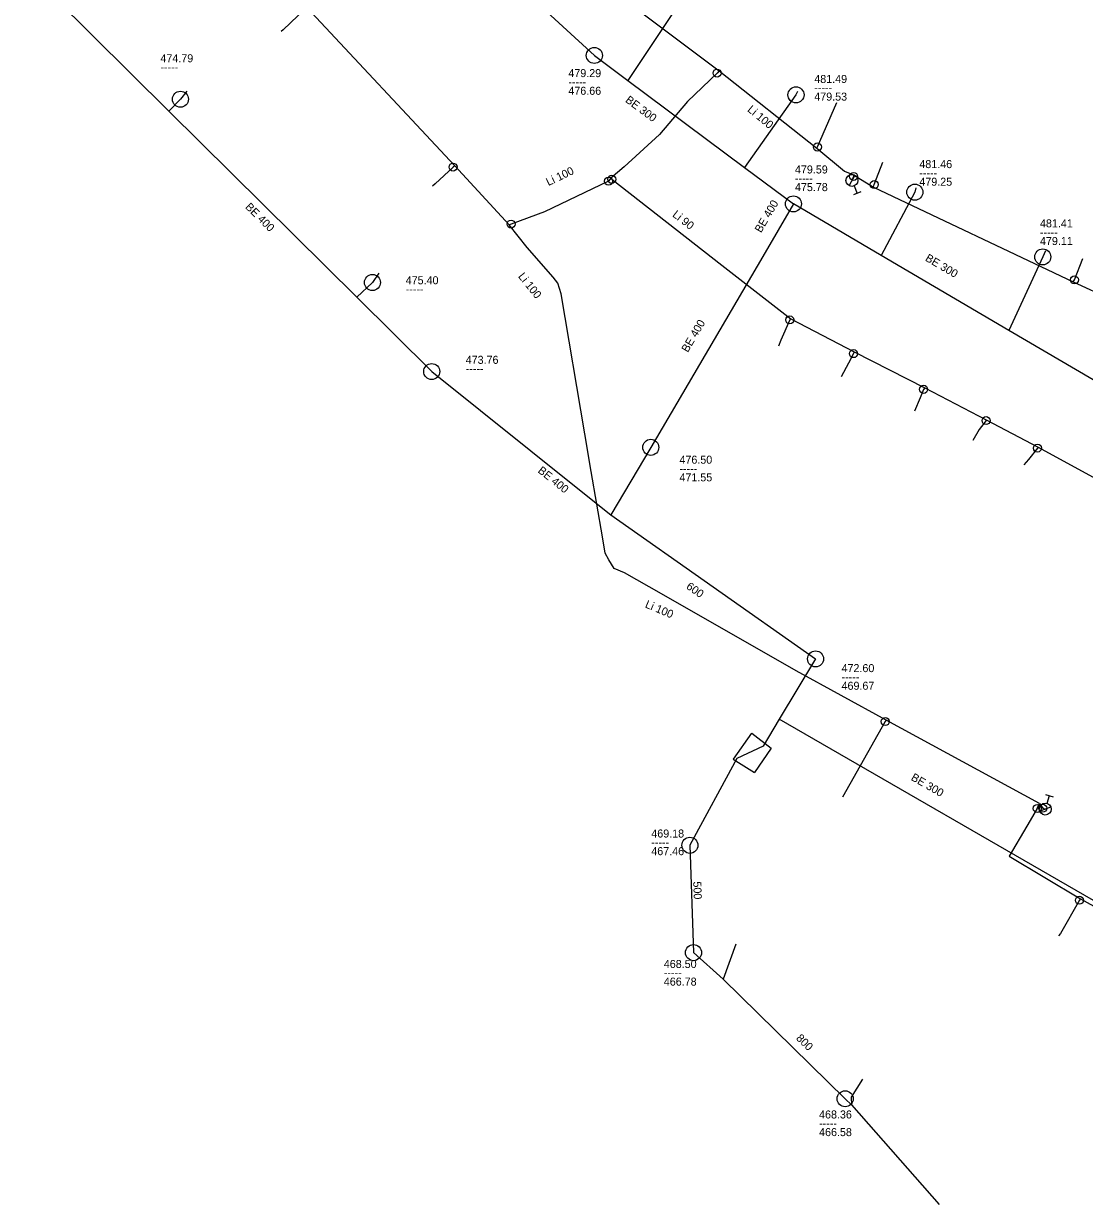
# Model space of a CAD drawing. Extents: x -685576 to -685145, y -1163436 to -1162895.
# Drawn here: x -685400.1 to -685267.9, y -1163416.2 to -1163269 of the extents above; entities that cross this region are included whole.
import ezdxf

# ---------------------------------------------------------------- set-up
doc = ezdxf.new("R2010")
doc.units = 0
doc.layers.add('Level 0', color=7, linetype='Continuous')

msp = doc.modelspace()

# ---------------------------------------------------------------- linework, layer by layer
at = {"layer": 'Level 0'}
for p, q in [((-685400.12, -1163261.95), (-685382.02, -1163279.88)), ((-685340, -1163262.77), (-685328.96, -1163272.95)), ((-685365.02, -1163267.13), (-685367.75, -1163269.74)), ((-685346.37, -1163286.69), (-685364.83, -1163266.94)), ((-685318.54, -1163266.73), (-685324.77, -1163276.07)), ((-685324.37, -1163266.65), (-685313.39, -1163274.86)), ((-685367.75, -1163269.74), (-685367.99, -1163269.96)), ((-685328.96, -1163272.95), (-685324.77, -1163276.07)), ((-685313.39, -1163274.86), (-685313.66, -1163275.14)), ((-685313.39, -1163274.86), (-685301.22, -1163284.5)), ((-685324.77, -1163276.07), (-685310.25, -1163286.9)), ((-685313.66, -1163275.14), (-685317.36, -1163278.7)), ((-685379.76, -1163277.4), (-685380.57, -1163278.41)), ((-685303.82, -1163277.86), (-685310.25, -1163286.9)), ((-685303.62, -1163277.45), (-685303.82, -1163277.86)), ((-685380.57, -1163278.41), (-685382.02, -1163279.88)), ((-685317.36, -1163278.7), (-685320.83, -1163282.81)), ((-685301.15, -1163284.36), (-685298.74, -1163278.82)), ((-685382.02, -1163279.88), (-685358.59, -1163303.09)), ((-685320.83, -1163282.81), (-685325.26, -1163286.83)), ((-685301.22, -1163284.5), (-685301.15, -1163284.36)), ((-685301.22, -1163284.5), (-685297.78, -1163287.36)), ((-685346.37, -1163286.69), (-685346.58, -1163286.86)), ((-685339.58, -1163294.07), (-685346.37, -1163286.69)), ((-685294.06, -1163289.04), (-685293, -1163286.26)), ((-685346.58, -1163286.86), (-685348.82, -1163288.94)), ((-685325.26, -1163286.83), (-685326.9, -1163288.26)), ((-685310.25, -1163286.9), (-685304.14, -1163291.45)), ((-685297.78, -1163287.36), (-685296.66, -1163287.81)), ((-685296.47, -1163287.87), (-685297.21, -1163289.17)), ((-685296.64, -1163288.03), (-685296.84, -1163288.52)), ((-685296.66, -1163287.81), (-685294.17, -1163289.38)), ((-685296.66, -1163287.81), (-685296.64, -1163288.03)), ((-685348.82, -1163288.94), (-685349.12, -1163289.26)), ((-685327.19, -1163288.62), (-685335.17, -1163292.44)), ((-685326.9, -1163288.26), (-685327.19, -1163288.62)), ((-685326.9, -1163288.26), (-685326.79, -1163288.39)), ((-685326.79, -1163288.39), (-685313.05, -1163299.09)), ((-685296.56, -1163289.21), (-685296.18, -1163290.14)), ((-685294.17, -1163289.38), (-685294.06, -1163289.04)), ((-685294.17, -1163289.38), (-685269.25, -1163301.17)), ((-685288.88, -1163289.44), (-685289, -1163289.99)), ((-685295.72, -1163289.95), (-685296.64, -1163290.33)), ((-685289, -1163289.99), (-685293.2, -1163297.88)), ((-685335.17, -1163292.44), (-685339.34, -1163293.97)), ((-685304.14, -1163291.45), (-685307.97, -1163297.99)), ((-685293.2, -1163297.88), (-685304.14, -1163291.45)), ((-685339.34, -1163293.97), (-685339.58, -1163294.07)), ((-685337.33, -1163296.89), (-685339.58, -1163294.07)), ((-685334.11, -1163300.6), (-685337.33, -1163296.89)), ((-685307.97, -1163297.99), (-685321.93, -1163321.8)), ((-685277.28, -1163307.23), (-685293.2, -1163297.88)), ((-685273.05, -1163298.06), (-685277.28, -1163307.23)), ((-685272.69, -1163297.29), (-685273.05, -1163298.06)), ((-685269.11, -1163300.92), (-685268.07, -1163298.27)), ((-685313.05, -1163299.09), (-685304.45, -1163305.78)), ((-685356.63, -1163301.25), (-685358.56, -1163303.06)), ((-685355.84, -1163300.09), (-685356.63, -1163301.25)), ((-685333.51, -1163301.35), (-685334.11, -1163300.6)), ((-685333.11, -1163302.67), (-685333.51, -1163301.35)), ((-685269.25, -1163301.17), (-685269.11, -1163300.92)), ((-685269.25, -1163301.17), (-685261.75, -1163304.63)), ((-685330.16, -1163320.11), (-685333.11, -1163302.67)), ((-685358.56, -1163303.06), (-685358.59, -1163303.09)), ((-685358.59, -1163303.09), (-685349.24, -1163312.35)), ((-685304.45, -1163305.78), (-685304.59, -1163305.91)), ((-685304.45, -1163305.78), (-685296.55, -1163309.9)), ((-685304.59, -1163305.91), (-685305.72, -1163308.42)), ((-685260.91, -1163316.85), (-685277.28, -1163307.23)), ((-685305.72, -1163308.42), (-685306.02, -1163309.17)), ((-685296.65, -1163310.12), (-685297.27, -1163311.3)), ((-685296.55, -1163309.9), (-685296.65, -1163310.12)), ((-685296.55, -1163309.9), (-685287.77, -1163314.37)), ((-685297.27, -1163311.3), (-685298.18, -1163313.03)), ((-685349.24, -1163312.35), (-685330.8, -1163327.11)), ((-685287.91, -1163314.57), (-685288.35, -1163315.61)), ((-685287.77, -1163314.37), (-685287.91, -1163314.57)), ((-685287.77, -1163314.37), (-685280.09, -1163318.38)), ((-685288.35, -1163315.61), (-685289.06, -1163317.27)), ((-685280.12, -1163318.47), (-685280.99, -1163319.59)), ((-685280.09, -1163318.38), (-685280.12, -1163318.47)), ((-685280.09, -1163318.38), (-685273.62, -1163321.79)), ((-685329.35, -1163324.82), (-685330.16, -1163320.11)), ((-685280.99, -1163319.59), (-685281.75, -1163320.94)), ((-685321.93, -1163321.8), (-685326.91, -1163330.22)), ((-685273.71, -1163321.9), (-685274.84, -1163323.31)), ((-685273.62, -1163321.79), (-685273.71, -1163321.9)), ((-685273.62, -1163321.79), (-685263.03, -1163327.59)), ((-685274.84, -1163323.31), (-685275.42, -1163323.97)), ((-685327.94, -1163332.97), (-685329.35, -1163324.82)), ((-685330.8, -1163327.11), (-685326.91, -1163330.22)), ((-685326.91, -1163330.22), (-685301.38, -1163348.17)), ((-685327.62, -1163334.98), (-685327.94, -1163332.97)), ((-685327.15, -1163335.84), (-685327.62, -1163334.98)), ((-685326.51, -1163336.91), (-685327.15, -1163335.84)), ((-685325.22, -1163337.45), (-685326.51, -1163336.91)), ((-685320.57, -1163340.07), (-685325.22, -1163337.45)), ((-685303.81, -1163349.68), (-685320.57, -1163340.07)), ((-685301.38, -1163348.17), (-685305.9, -1163355.68)), ((-685292.59, -1163355.81), (-685303.81, -1163349.68)), ((-685305.9, -1163355.68), (-685307.93, -1163359.03)), ((-685258.67, -1163382.95), (-685305.9, -1163355.68)), ((-685292.59, -1163355.81), (-685292.69, -1163355.98)), ((-685273.46, -1163366.21), (-685292.59, -1163355.81)), ((-685292.69, -1163355.98), (-685298.03, -1163365.42)), ((-685309.35, -1163357.41), (-685311.67, -1163360.66)), ((-685309.34, -1163357.42), (-685306.91, -1163359.28)), ((-685307.93, -1163359.03), (-685311.2, -1163360.6)), ((-685306.91, -1163359.28), (-685308.98, -1163362.32)), ((-685311.2, -1163360.6), (-685317.05, -1163371.41)), ((-685311.67, -1163360.66), (-685308.98, -1163362.32)), ((-685272.7, -1163365.07), (-685271.74, -1163365.37)), ((-685272.52, -1163366.17), (-685272.22, -1163365.22)), ((-685273.74, -1163366.82), (-685275.02, -1163369.01)), ((-685273.74, -1163366.82), (-685273.46, -1163366.21)), ((-685273.46, -1163366.21), (-685273.06, -1163366.79)), ((-685273.44, -1163367.16), (-685272.04, -1163366.62)), ((-685273.06, -1163366.79), (-685272.74, -1163366.89)), ((-685275.02, -1163369.01), (-685277.23, -1163372.76)), ((-685317.05, -1163371.41), (-685316.6, -1163384.79)), ((-685277.23, -1163372.76), (-685268.35, -1163378.09)), ((-685268.48, -1163378.26), (-685270.83, -1163382.4)), ((-685268.35, -1163378.09), (-685268.48, -1163378.26)), ((-685268.35, -1163378.09), (-685232.79, -1163397.77)), ((-685270.83, -1163382.4), (-685271.07, -1163382.7)), ((-685311.3, -1163383.73), (-685312.9, -1163388.11)), ((-685316.6, -1163384.79), (-685312.9, -1163388.11)), ((-685312.9, -1163388.11), (-685297.69, -1163403)), ((-685295.51, -1163400.57), (-685296.93, -1163402.8)), ((-685297.69, -1163403), (-685296.91, -1163403.76)), ((-685296.93, -1163402.8), (-685296.91, -1163403.76)), ((-685296.91, -1163403.76), (-685285.96, -1163416.17))]:
    msp.add_line(p, q, dxfattribs=at)
for centre, radius in [((-685328.96, -1163272.95), 1), ((-685313.66, -1163275.14), 0.5), ((-685380.57, -1163278.41), 1), ((-685303.82, -1163277.86), 1), ((-685301.15, -1163284.36), 0.5), ((-685346.58, -1163286.86), 0.5), ((-685327.19, -1163288.62), 0.5), ((-685326.79, -1163288.39), 0.5), ((-685296.84, -1163288.52), 0.75), ((-685296.64, -1163288.03), 0.5), ((-685294.06, -1163289.04), 0.5), ((-685289, -1163289.99), 1), ((-685304.14, -1163291.45), 1), ((-685339.34, -1163293.97), 0.5), ((-685273.05, -1163298.06), 1), ((-685356.63, -1163301.25), 1), ((-685269.11, -1163300.92), 0.5), ((-685304.59, -1163305.91), 0.5), ((-685296.65, -1163310.12), 0.5), ((-685349.24, -1163312.35), 1), ((-685287.91, -1163314.57), 0.5), ((-685280.12, -1163318.47), 0.5), ((-685321.93, -1163321.8), 1), ((-685273.71, -1163321.9), 0.5), ((-685301.38, -1163348.17), 1), ((-685292.69, -1163355.98), 0.5), ((-685272.74, -1163366.89), 0.75), ((-685273.74, -1163366.82), 0.5), ((-685273.06, -1163366.79), 0.5), ((-685317.05, -1163371.41), 1), ((-685268.48, -1163378.26), 0.5), ((-685316.6, -1163384.79), 1), ((-685297.69, -1163403), 1)]:
    msp.add_circle(centre, radius, dxfattribs=at)

# ---------------------------------------------------------------- texts
for s, p in [('474.79', (-685383.06, -1163273.8)), ('-----', (-685383.06, -1163274.9)), ('479.29', (-685332.2, -1163275.65)), ('-----', (-685332.2, -1163276.75)), ('481.49', (-685301.54, -1163276.38)), ('476.66', (-685332.2, -1163277.85)), ('479.53', (-685301.54, -1163278.58)), ('-----', (-685301.54, -1163277.48)), ('479.59', (-685303.95, -1163287.66)), ('481.46', (-685288.44, -1163286.99)), ('479.25', (-685288.44, -1163289.19)), ('-----', (-685288.44, -1163288.09)), ('475.78', (-685303.95, -1163289.86)), ('-----', (-685303.95, -1163288.76)), ('481.41', (-685273.4, -1163294.38)), ('-----', (-685273.4, -1163295.48)), ('479.11', (-685273.4, -1163296.58)), ('475.40', (-685352.48, -1163301.47)), ('-----', (-685352.48, -1163302.57)), ('473.76', (-685345, -1163311.39)), ('-----', (-685345, -1163312.49)), ('476.50', (-685318.35, -1163323.84)), ('-----', (-685318.35, -1163324.94)), ('471.55', (-685318.35, -1163326.04)), ('472.60', (-685298.14, -1163349.82)), ('469.67', (-685298.14, -1163352.02)), ('-----', (-685298.14, -1163350.92)), ('469.18', (-685321.86, -1163370.44)), ('467.46', (-685321.86, -1163372.64)), ('-----', (-685321.86, -1163371.54)), ('468.50', (-685320.3, -1163386.7)), ('466.78', (-685320.3, -1163388.9)), ('-----', (-685320.3, -1163387.8)), ('468.36', (-685300.94, -1163405.46)), ('466.58', (-685300.94, -1163407.66)), ('-----', (-685300.94, -1163406.56))]:
    msp.add_text(s, height=1, dxfattribs=at).set_placement(p)
for s, rotation, p in [('BE 300', 323.3, (-685325.18, -1163278.68)), ('Li 100', 320.26, (-685309.96, -1163279.83)), ('Li 100', 25.58, (-685334.69, -1163289.24)), ('BE 400', 59.646, (-685308.18, -1163295.13)), ('BE 400', 315.273, (-685372.56, -1163291.92)), ('Li 90', 322.09, (-685319.31, -1163292.95)), ('BE 300', 329.565, (-685287.79, -1163298.48)), ('Li 100', 308.66, (-685338.52, -1163300.51)), ('BE 400', 59.617, (-685317.31, -1163310.04)), ('BE 400', 321.325, (-685336.09, -1163324.85)), ('600', 324.889, (-685317.59, -1163339.34)), ('Li 100', 337.286, (-685322.72, -1163341.73)), ('BE 300', 330.004, (-685289.57, -1163363.22)), ('500', 271.926, (-685316.63, -1163375.93)), ('800', 315.609, (-685303.88, -1163395.54))]:
    msp.add_text(s, height=1, rotation=rotation, dxfattribs=at).set_placement(p)

doc.saveas('drawing.dxf')
